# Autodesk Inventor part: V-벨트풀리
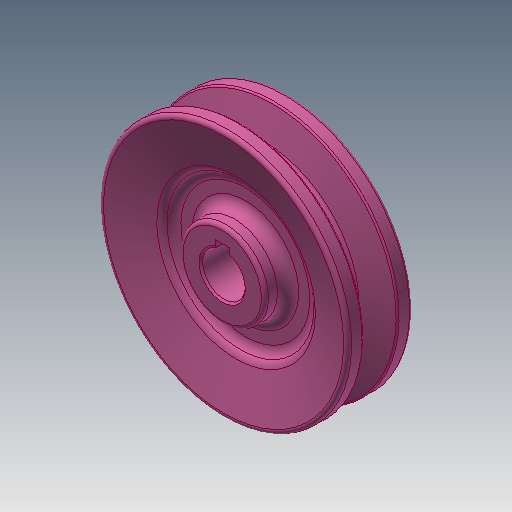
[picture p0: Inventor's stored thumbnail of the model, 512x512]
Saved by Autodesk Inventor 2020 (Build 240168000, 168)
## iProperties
Created: 2016-08
Part Number: V-벨트풀리
Material: 알루미늄 6061
Document SubType Name: Modeling
Designer: mduedu
Density: 2.71 g/cm^3
Appearance: 분홍색
Author: mduedu
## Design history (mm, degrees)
sketch "스케치1"
  geometry: L1 (0, 9.5)-(0, -9.5); L2 (0, 9.5)-(35, 9.5); L3 (35, 9.5)-(35, 4.825); L4 (35, 4.825)-(26, 2.074); L5 (26, 2.074)-(26, 0); L6 (0, 0)-(26, 0); L7 (0, -9.5)-(35, -9.5); L8 (35, -9.5)-(35, -4.825); L9 (35, -4.825)-(26, -2.074); L10 (26, -2.074)-(26, 0); L11 (32.3, 9.5)-(32.3, -9.5); 3 further points
  constraints: 22 end point, 6 point on line, 4 perpendicular, 3 symmetric about line, 1 coincident, 1 horizontal alignment, 1 midpoint, 1 parallel, 1 vertical
  dimensions: "d0" = 19 distance of L1.start L1.end; "d2" = 70 diameter of L8 L1; "d4" = 6.3 distance between parallel lines of L10 L11; "d5" = 2.7 distance between parallel lines of L11 L8; "d6" = 8 distance of point (32.3, -4) point (32.3, 4); "d7" = 34 deg angle of L9 L4
revolve "회전1" sketch "스케치1" stored, may be unused: angle "d8" = 90 deg
sketch "스케치2"
  geometry: L1 (-2, 0)-(2, 0); L2 (2, 0)-(2, 7.8); L3 (2, 7.8)-(-2, 7.8); L4 (-2, 7.8)-(-2, 0); C1 r 6 at (0, 0); 2 further points
  constraints: 8 end point, 2 coincident, 2 parallel, 1 centre point, 1 horizontal, 1 midpoint, 1 perpendicular
  dimensions: "d9" = 12 diameter of C1; "d11" = 4 distance of L2.end L3.end; "d12" = 7.8 distance of L1.end L2.end
extrude "돌출1" cut sketch "스케치2" extent not by distance; stored distance "d13" = 10; taper "d14" = 0 deg
sketch "스케치3"
  geometry: L1 (35, 4.825)-(26, 2.074) reference; L2 (26, 2.074)-(26, -2.074) reference; L3 (0, 0)-(26, 0); L4 (35, 9.5)-(35, 4.825) reference; L5 (-35, 9.5)-(35, 9.5) reference; L6 (35, 9.5)-(21, 5.22); L7 (21, 5.22)-(21, 3); L8 (21, 3)-(12, 3); L9 (12, 3)-(12, 9.5); L10 (0, 9.5)-(0, -9.5); L11 (5.657, -9.5)-(-6, -9.5) reference; L12 (12, 9.5)-(35, 9.5)
  constraints: 14 end point, 3 midpoint, 2 parallel, 2 perpendicular, 2 point on line, 1 collinear, 1 horizontal
  dimensions: "d15" = 3 distance between parallel lines of L3 L8; "d17" = 42 diameter of L7 L10; "d18" = 24 diameter of L9 L10
revolve "회전2" sketch "스케치3" stored, may be unused: angle "d19" = 90 deg
fillet "모깎기1" dims "d20" = 0.5, "d21" = 1, "d22" = 1
fillet "모깎기2" dims "d23" = 3
fillet "모깎기3" dims "d24" = 3
fillet "모깎기4" dims "d25" = 3
chamfer "모따기1" distance "d26" = 0.5; stored, may be unused: second distance "d27" = 2, angle "d28" = 45 deg
fillet "모깎기5" dims "d29" = 1
node "솔리드1"
mirror "대칭1"
